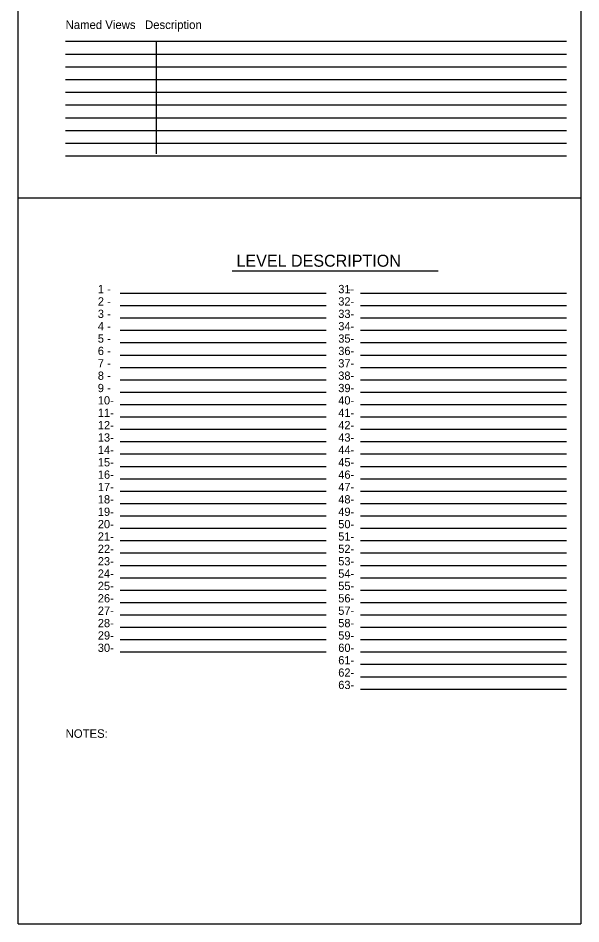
# Model space of a CAD drawing. Extents: x 9999.96 to 10005.26, y 9999.88 to 10002.38.
# Drawn here: x 10003.534 to 10004.245, y 9999.912 to 10001.056 of the extents above; entities that cross this region are included whole.
import ezdxf

# ---------------------------------------------------------------- set-up
doc = ezdxf.new("R2010")
doc.units = 0
doc.layers.add('Level 8', color=7, linetype='Continuous')

msp = doc.modelspace()

# ---------------------------------------------------------------- linework, layer by layer
at = {"layer": 'Level 8'}
for p, q in [((10003.5343, 9999.912), (10003.5343, 10001.7453)), ((10004.2454, 10001.7453), (10004.2454, 9999.912)), ((10004.2274, 10001.0263), (10003.5943, 10001.0263)), ((10003.7087, 10001.0263), (10003.7087, 10000.8848)), ((10004.2274, 10001.0102), (10003.5943, 10001.0102)), ((10004.2274, 10000.9941), (10003.5943, 10000.9941)), ((10004.2274, 10000.978), (10003.5943, 10000.978)), ((10004.2274, 10000.962), (10003.5943, 10000.962)), ((10004.2274, 10000.9459), (10003.5943, 10000.9459)), ((10004.2274, 10000.9298), (10003.5943, 10000.9298)), ((10004.2274, 10000.9137), (10003.5943, 10000.9137)), ((10004.2274, 10000.8977), (10003.5943, 10000.8977)), ((10004.2274, 10000.8816), (10003.5943, 10000.8816)), ((10004.2454, 10000.8286), (10003.5343, 10000.8286)), ((10003.8048, 10000.7369), (10004.0652, 10000.7369)), ((10003.6631, 10000.7086), (10003.9235, 10000.7086)), ((10003.9669, 10000.7086), (10004.2274, 10000.7086)), ((10003.6631, 10000.693), (10003.9235, 10000.693)), ((10003.9669, 10000.693), (10004.2274, 10000.693)), ((10003.6631, 10000.6773), (10003.9235, 10000.6773)), ((10003.9669, 10000.6773), (10004.2274, 10000.6773)), ((10003.6631, 10000.6617), (10003.9235, 10000.6617)), ((10003.9669, 10000.6617), (10004.2274, 10000.6617)), ((10003.6631, 10000.6461), (10003.9235, 10000.6461)), ((10003.9669, 10000.6461), (10004.2274, 10000.6461)), ((10003.6631, 10000.6305), (10003.9235, 10000.6305)), ((10003.9669, 10000.6305), (10004.2274, 10000.6305)), ((10003.6631, 10000.6148), (10003.9235, 10000.6148)), ((10003.9669, 10000.6148), (10004.2274, 10000.6148)), ((10003.6631, 10000.5992), (10003.9235, 10000.5992)), ((10003.9669, 10000.5992), (10004.2274, 10000.5992)), ((10003.6631, 10000.5836), (10003.9235, 10000.5836)), ((10003.9669, 10000.5836), (10004.2274, 10000.5836)), ((10003.6631, 10000.568), (10003.9235, 10000.568)), ((10003.9669, 10000.568), (10004.2274, 10000.568)), ((10003.6631, 10000.5523), (10003.9235, 10000.5523)), ((10003.9669, 10000.5523), (10004.2274, 10000.5523)), ((10003.6631, 10000.5367), (10003.9235, 10000.5367)), ((10003.9669, 10000.5367), (10004.2274, 10000.5367)), ((10003.6631, 10000.5211), (10003.9235, 10000.5211)), ((10003.9669, 10000.5211), (10004.2274, 10000.5211)), ((10003.6631, 10000.5055), (10003.9235, 10000.5055)), ((10003.9669, 10000.5055), (10004.2274, 10000.5055)), ((10003.6631, 10000.4898), (10003.9235, 10000.4898)), ((10003.9669, 10000.4898), (10004.2274, 10000.4898)), ((10003.6631, 10000.4742), (10003.9235, 10000.4742)), ((10003.9669, 10000.4742), (10004.2274, 10000.4742)), ((10003.6631, 10000.4586), (10003.9235, 10000.4586)), ((10003.9669, 10000.4586), (10004.2274, 10000.4586)), ((10003.6631, 10000.443), (10003.9235, 10000.443)), ((10003.9669, 10000.443), (10004.2274, 10000.443)), ((10003.6631, 10000.4273), (10003.9235, 10000.4273)), ((10003.9669, 10000.4273), (10004.2274, 10000.4273)), ((10003.6631, 10000.4117), (10003.9235, 10000.4117)), ((10003.9669, 10000.4117), (10004.2274, 10000.4117)), ((10003.6631, 10000.3961), (10003.9235, 10000.3961)), ((10003.9669, 10000.3961), (10004.2274, 10000.3961)), ((10003.6631, 10000.3805), (10003.9235, 10000.3805)), ((10003.9669, 10000.3805), (10004.2274, 10000.3805)), ((10003.6631, 10000.3648), (10003.9235, 10000.3648)), ((10003.9669, 10000.3648), (10004.2274, 10000.3648)), ((10003.6631, 10000.3492), (10003.9235, 10000.3492)), ((10003.9669, 10000.3492), (10004.2274, 10000.3492)), ((10003.6631, 10000.3336), (10003.9235, 10000.3336)), ((10003.9669, 10000.3336), (10004.2274, 10000.3336)), ((10003.6631, 10000.318), (10003.9235, 10000.318)), ((10003.9669, 10000.318), (10004.2274, 10000.318)), ((10003.6631, 10000.3023), (10003.9235, 10000.3023)), ((10003.9669, 10000.3023), (10004.2274, 10000.3023)), ((10003.6631, 10000.2867), (10003.9235, 10000.2867)), ((10003.9669, 10000.2867), (10004.2274, 10000.2867)), ((10003.6631, 10000.2711), (10003.9235, 10000.2711)), ((10003.9669, 10000.2711), (10004.2274, 10000.2711)), ((10003.6631, 10000.2555), (10003.9235, 10000.2555)), ((10003.9669, 10000.2555), (10004.2274, 10000.2555)), ((10003.9669, 10000.2398), (10004.2274, 10000.2398)), ((10003.9669, 10000.2242), (10004.2274, 10000.2242)), ((10003.9669, 10000.2086), (10004.2274, 10000.2086)), ((10003.5343, 9999.912), (10004.2454, 9999.912))]:
    msp.add_line(p, q, dxfattribs=at)

# ---------------------------------------------------------------- texts
for s, height, p in [('Named Views   Description', 0.010717, (10003.5943, 10001.0423)), ('LEVEL DESCRIPTION', 0.015191, (10003.8102, 10000.742)), ('1 -', 0.01042, (10003.635, 10000.7086)), ('31-', 0.01042, (10003.9388, 10000.7086)), ('3 -', 0.01042, (10003.9388, 10000.7086)), ('2 -', 0.01042, (10003.635, 10000.693)), ('32-', 0.01042, (10003.9388, 10000.693)), ('3 -', 0.01042, (10003.635, 10000.6773)), ('33-', 0.01042, (10003.9388, 10000.6773)), ('4 -', 0.01042, (10003.635, 10000.6617)), ('34-', 0.01042, (10003.9388, 10000.6617)), ('5 -', 0.01042, (10003.635, 10000.6461)), ('35-', 0.01042, (10003.9388, 10000.6461)), ('6 -', 0.01042, (10003.635, 10000.6305)), ('36-', 0.01042, (10003.9388, 10000.6305)), ('7 -', 0.01042, (10003.635, 10000.6148)), ('37-', 0.01042, (10003.9388, 10000.6148)), ('8 -', 0.01042, (10003.635, 10000.5992)), ('38-', 0.01042, (10003.9388, 10000.5992)), ('9 -', 0.01042, (10003.635, 10000.5836)), ('39-', 0.01042, (10003.9388, 10000.5836)), ('10-', 0.01042, (10003.635, 10000.568)), ('40-', 0.01042, (10003.9388, 10000.568)), ('11-', 0.01042, (10003.635, 10000.5523)), ('41-', 0.01042, (10003.9388, 10000.5523)), ('12-', 0.01042, (10003.635, 10000.5367)), ('42-', 0.01042, (10003.9388, 10000.5367)), ('13-', 0.01042, (10003.635, 10000.5211)), ('43-', 0.01042, (10003.9388, 10000.5211)), ('14-', 0.01042, (10003.635, 10000.5055)), ('44-', 0.01042, (10003.9388, 10000.5055)), ('15-', 0.01042, (10003.635, 10000.4898)), ('45-', 0.01042, (10003.9388, 10000.4898)), ('16-', 0.01042, (10003.635, 10000.4742)), ('46-', 0.01042, (10003.9388, 10000.4742)), ('17-', 0.01042, (10003.635, 10000.4586)), ('47-', 0.01042, (10003.9388, 10000.4586)), ('18-', 0.01042, (10003.635, 10000.443)), ('48-', 0.01042, (10003.9388, 10000.443)), ('19-', 0.01042, (10003.635, 10000.4273)), ('49-', 0.01042, (10003.9388, 10000.4273)), ('20-', 0.01042, (10003.635, 10000.4117)), ('50-', 0.01042, (10003.9388, 10000.4117)), ('21-', 0.01042, (10003.635, 10000.3961)), ('51-', 0.01042, (10003.9388, 10000.3961)), ('22-', 0.01042, (10003.635, 10000.3805)), ('52-', 0.01042, (10003.9388, 10000.3805)), ('23-', 0.01042, (10003.635, 10000.3648)), ('53-', 0.01042, (10003.9388, 10000.3648)), ('24-', 0.01042, (10003.635, 10000.3492)), ('54-', 0.01042, (10003.9388, 10000.3492)), ('25-', 0.01042, (10003.635, 10000.3336)), ('55-', 0.01042, (10003.9388, 10000.3336)), ('26-', 0.01042, (10003.635, 10000.318)), ('56-', 0.01042, (10003.9388, 10000.318)), ('27-', 0.01042, (10003.635, 10000.3023)), ('57-', 0.01042, (10003.9388, 10000.3023)), ('28-', 0.01042, (10003.635, 10000.2867)), ('58-', 0.01042, (10003.9388, 10000.2867)), ('29-', 0.01042, (10003.635, 10000.2711)), ('59-', 0.01042, (10003.9388, 10000.2711)), ('30-', 0.01042, (10003.635, 10000.2555)), ('60-', 0.01042, (10003.9388, 10000.2555)), ('61-', 0.01042, (10003.9388, 10000.2398)), ('62-', 0.01042, (10003.9388, 10000.2242)), ('63-', 0.01042, (10003.9388, 10000.2086)), ('NOTES:', 0.01072, (10003.5943, 10000.147))]:
    msp.add_text(s, height=height, dxfattribs=at).set_placement(p)

doc.saveas('drawing.dxf')
